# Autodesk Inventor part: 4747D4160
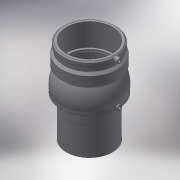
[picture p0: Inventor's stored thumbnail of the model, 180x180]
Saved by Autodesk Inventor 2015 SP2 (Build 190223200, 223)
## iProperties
Created: 2017-08
Part Number: 4747D4160
Material: Generic
Description: PLASSON WASTEWATER ADJUSTABLE ELBOW ONE SIDED 160
Document SubType Name: Modeling
Designer: Кирилл
Density: 1 g/cm^3
Appearance: Default
Author: Кирилл
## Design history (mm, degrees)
derived "4747D4.ipt"
feature "Solid1::4747D4.ipt"
tag "TaggingFeature1"
body "Solid1"
other parameters: "d0" = 160.92, "d2" = 78, "d3" = 45 deg, "d4" = 184, "d5" = 176, "d6" = 141.6096, "d7" = 128.736, "d8" = 144, "d13" = 45 deg, "d15" = 135 deg, "d17" = 193, "d18" = 45 deg, "d19" = 80.46, "d22" = 4, "d23" = 16.092, "d25" = 45 deg, "d26" = 15 deg, "d27" = 298, "d28" = 141, "d58" = 105, "d59" = 15, "d61" = 5 deg, "d62" = 15, "d65" = 4, "d66" = 4, "d67" = 14, "d68" = 0, "d69" = 3, "d70" = 0, "d71" = 98, "d72" = 156.8, "H_" = 202, "A_" = 105, "L_1" = 78, "D_" = 193, "L_" = 298, "L_2" = 98, "D_1" = 141, "d_1" = 1, "d21" = 4
